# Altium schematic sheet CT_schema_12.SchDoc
size 742 x 377 mm
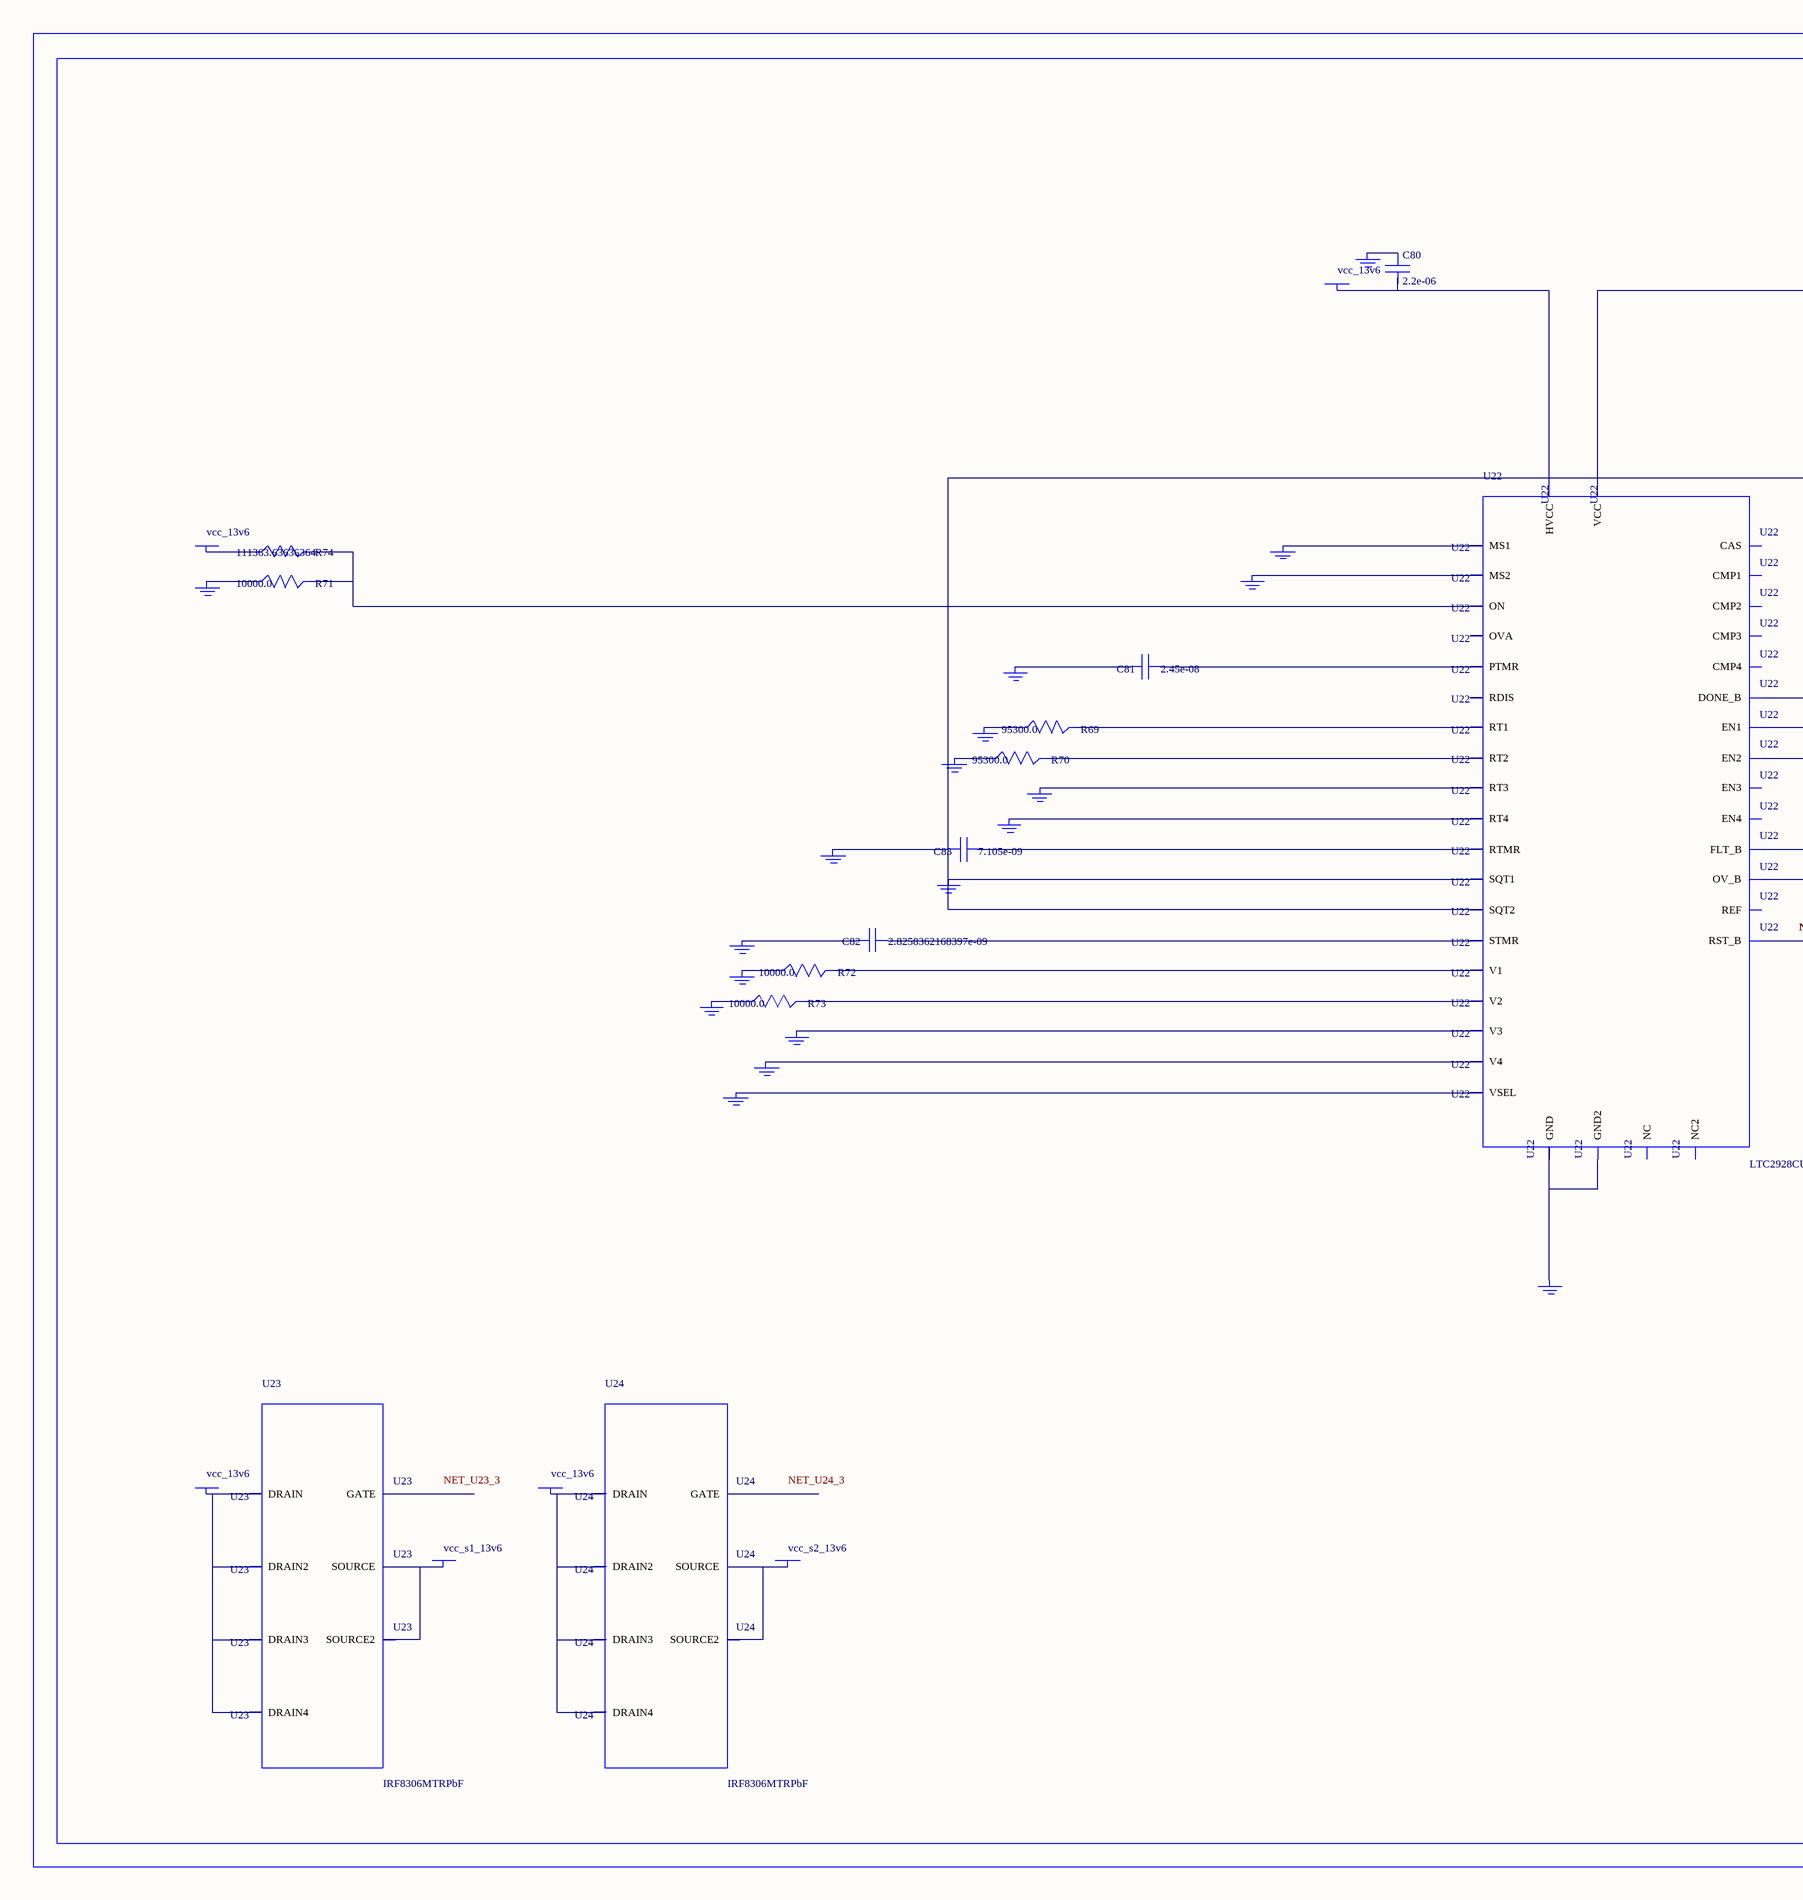
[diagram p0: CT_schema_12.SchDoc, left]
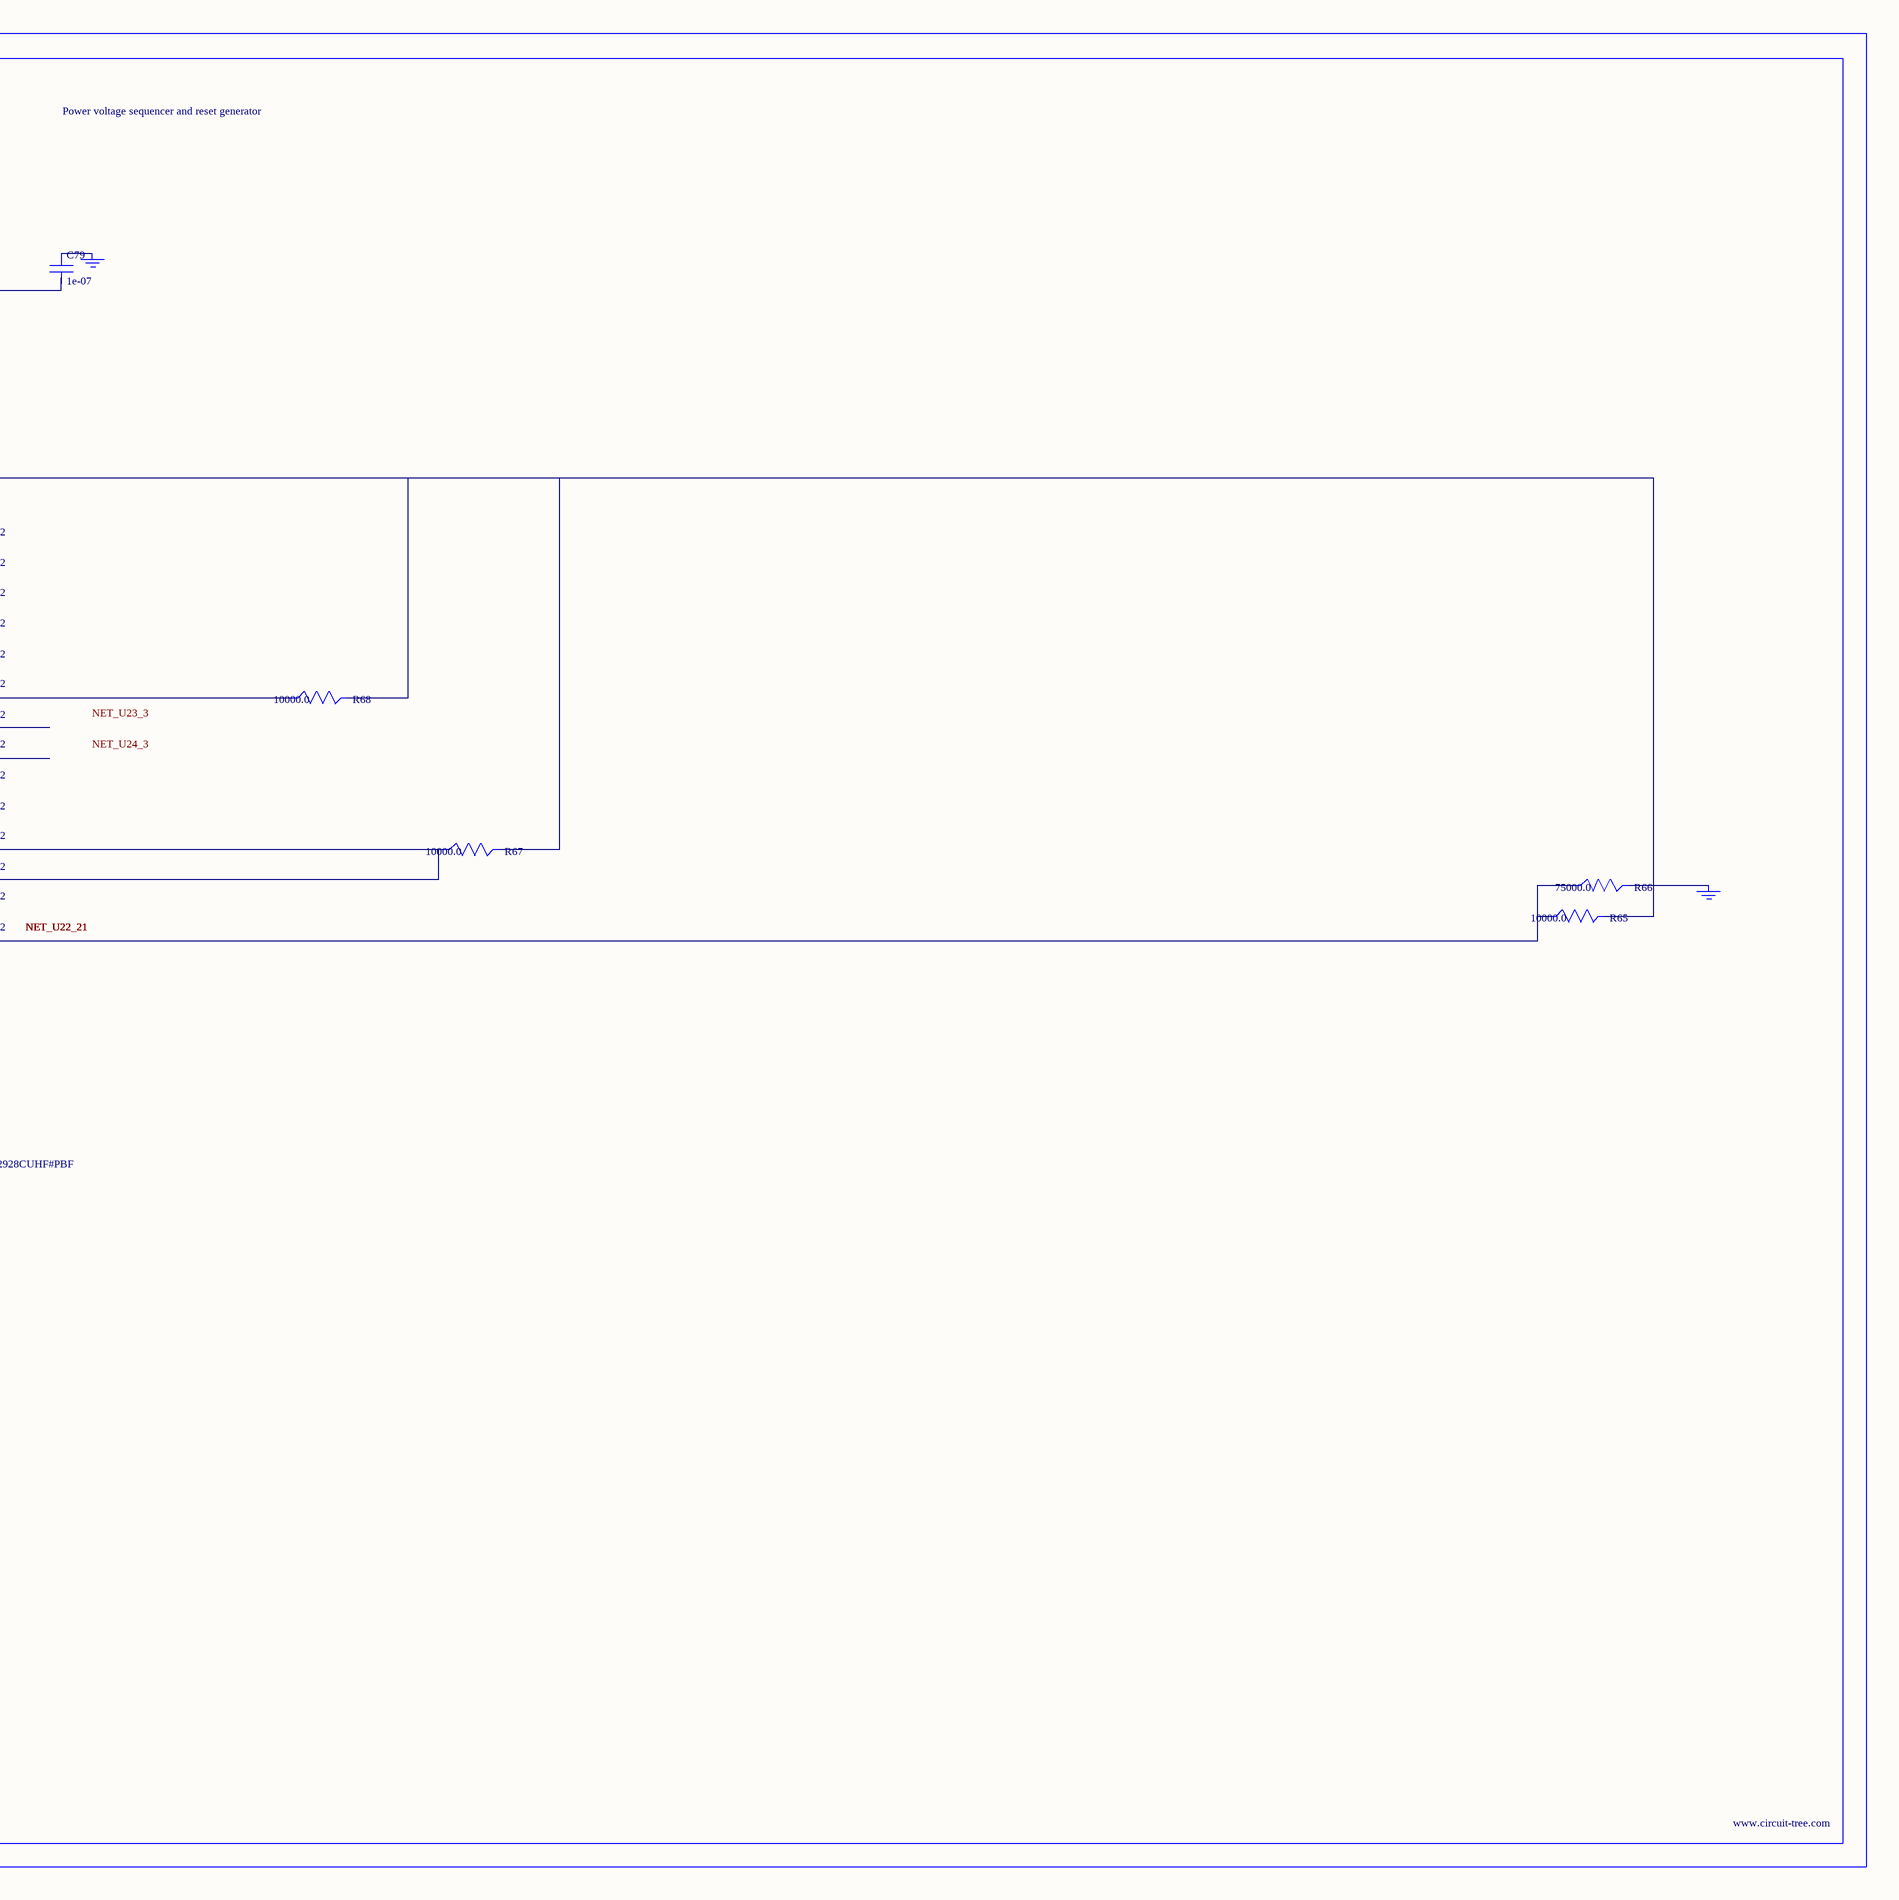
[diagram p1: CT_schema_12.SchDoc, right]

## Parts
BORDER11  (no value)
C79  1e-07  [C0402]
C80  2.2e-06  [C0603]
C81  2.45e-08  [R0603]
C82  2.8258362168397e-09  [R0603]
C83  7.105e-09  [R0603]
GND_INSTANCE_11_0  (no value)
GND_INSTANCE_11_1  (no value)
GND_INSTANCE_11_2  (no value)
GND_INSTANCE_11_3  (no value)
GND_INSTANCE_11_4  (no value)
GND_INSTANCE_11_5  (no value)
GND_INSTANCE_11_6  (no value)
GND_INSTANCE_11_7  (no value)
GND_INSTANCE_11_8  (no value)
GND_INSTANCE_11_9  (no value)
GND_INSTANCE_11_10  (no value)
GND_INSTANCE_11_11  (no value)
GND_INSTANCE_11_12  (no value)
GND_INSTANCE_11_13  (no value)
GND_INSTANCE_11_14  (no value)
GND_INSTANCE_11_15  (no value)
GND_INSTANCE_11_16  (no value)
GND_INSTANCE_11_17  (no value)
GND_INSTANCE_11_18  (no value)
GND_INSTANCE_11_19  (no value)
POWER_INSTANCE_11_0  vcc_13v6
POWER_INSTANCE_11_1  vcc_13v6
POWER_INSTANCE_11_2  vcc_13v6
POWER_INSTANCE_11_3  vcc_s1_13v6
POWER_INSTANCE_11_4  vcc_13v6
POWER_INSTANCE_11_5  vcc_s2_13v6
R65  10000.0  [R0603]
R66  75000.0  [R0603]
R67  10000.0  [R0603]
R68  10000.0  [R0603]
R69  95300.0  [R0603]
R70  95300.0  [R0603]
R71  10000.0  [R0603]
R72  10000.0  [R0603]
R73  10000.0  [R0603]
R74  111363.63636364  [R0603]
U22  LTC2928CUHF#PBF  [QFN-38_UHF]
U23  IRF8306MTRPbF  [IRF8306MTRPBF]
U24  IRF8306MTRPbF  [IRF8306MTRPBF]

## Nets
NetC79_1: C79.1 GND_INSTANCE_11_10.0(GND)
NetC79_2: C79.2 C83.2 GND_INSTANCE_11_5.0(GND) GND_INSTANCE_11_15.0(GND) R65.2 R67.2 R68.2 U22.10(SQT1) U22.11(SQT2) U22.22(VCC)
NetC80_1: C80.1 GND_INSTANCE_11_11.0(GND)
NetC80_2: C80.2 POWER_INSTANCE_11_1.0(PWR) U22.23(HVCC)
NetC81_1: C81.1 U22.27(PTMR)
NetC81_2: C81.2 GND_INSTANCE_11_14.0(GND)
NetC82_1: C82.1 U22.26(STMR)
NetC82_2: C82.2 GND_INSTANCE_11_13.0(GND)
NetC83_1: C83.1 U22.28(RTMR)
NetGND_INSTANCE_11_0_0: GND_INSTANCE_11_0.0(GND) R72.1
NetGND_INSTANCE_11_1_0: GND_INSTANCE_11_1.0(GND) R69.1
NetGND_INSTANCE_11_2_0: GND_INSTANCE_11_2.0(GND) R70.1
NetGND_INSTANCE_11_3_0: GND_INSTANCE_11_3.0(GND) U22.8(RT3)
NetGND_INSTANCE_11_4_0: GND_INSTANCE_11_4.0(GND) U22.9(RT4)
NetGND_INSTANCE_11_6_0: GND_INSTANCE_11_6.0(GND) U22.12(MS1)
NetGND_INSTANCE_11_7_0: GND_INSTANCE_11_7.0(GND) U22.13(MS2)
NetGND_INSTANCE_11_8_0: GND_INSTANCE_11_8.0(GND) R71.1
NetGND_INSTANCE_11_9_0: GND_INSTANCE_11_9.0(GND) R66.2
NetGND_INSTANCE_11_12_0: GND_INSTANCE_11_12.0(GND) U22.25(VSEL)
NetGND_INSTANCE_11_16_0: GND_INSTANCE_11_16.0(GND) U22.30(V4)
NetGND_INSTANCE_11_17_0: GND_INSTANCE_11_17.0(GND) U22.32(V3)
NetGND_INSTANCE_11_18_0: GND_INSTANCE_11_18.0(GND) R73.1
NetGND_INSTANCE_11_19_0: GND_INSTANCE_11_19.0(GND) U22.24(GND) U22.39(GND2)
NetPOWER_INSTANCE_11_0_0: POWER_INSTANCE_11_0.0(PWR) R74.1
NetPOWER_INSTANCE_11_2_0: POWER_INSTANCE_11_2.0(PWR) U23.1(DRAIN) U23.2(DRAIN2) U23.6(DRAIN3) U23.7(DRAIN4)
NetPOWER_INSTANCE_11_3_0: POWER_INSTANCE_11_3.0(PWR) U23.4(SOURCE) U23.5(SOURCE2)
NetPOWER_INSTANCE_11_4_0: POWER_INSTANCE_11_4.0(PWR) U24.1(DRAIN) U24.2(DRAIN2) U24.6(DRAIN3) U24.7(DRAIN4)
NetPOWER_INSTANCE_11_5_0: POWER_INSTANCE_11_5.0(PWR) U24.4(SOURCE) U24.5(SOURCE2)
NetR65_1: R65.1 R66.1 U22.21(RST_B)
NetR67_1: R67.1 U22.19(FLT_B) U22.20(OV_B)
NetR68_1: R68.1 U22.18(DONE_B)
NetR69_2: R69.2 U22.6(RT1)
NetR70_2: R70.2 U22.7(RT2)
NetR71_2: R71.2 R74.2 U22.16(ON)
NetR72_2: R72.2 U22.3(V1)
NetR73_2: R73.2 U22.38(V2)

Not connected (* = marked no-connect by the designer): U22 1(OVA) 2(EN1) 4(NC) 5(REF) 14(RDIS) 15(CAS) 17(NC2) 29(EN4) 31(EN3) 33(CMP3) 34(CMP4) 35(CMP1) 36(CMP2) 37(EN2); U23 3(GATE); U24 3(GATE)

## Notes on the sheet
- Labels drawn without touching a wire or pin: NET_U23_3, NET_U24_3

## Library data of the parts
BORDER11 = BORDER_PAGE11
C79 = C0402C104K3RACTU
C80 = GRM188R61H225KE1115D
C81 = C81
C82 = C82
C83 = C83
GND_INSTANCE_11_0-GND_INSTANCE_11_19 = GND
POWER_INSTANCE_11_0-POWER_INSTANCE_11_5 = PWR
R65 R67 R68 R71-R73 = RC0603JR-0710KL
R66 = RC0603JR-0775KL
R69 R70 = RC0603FR-0795K3L
R74 = R74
